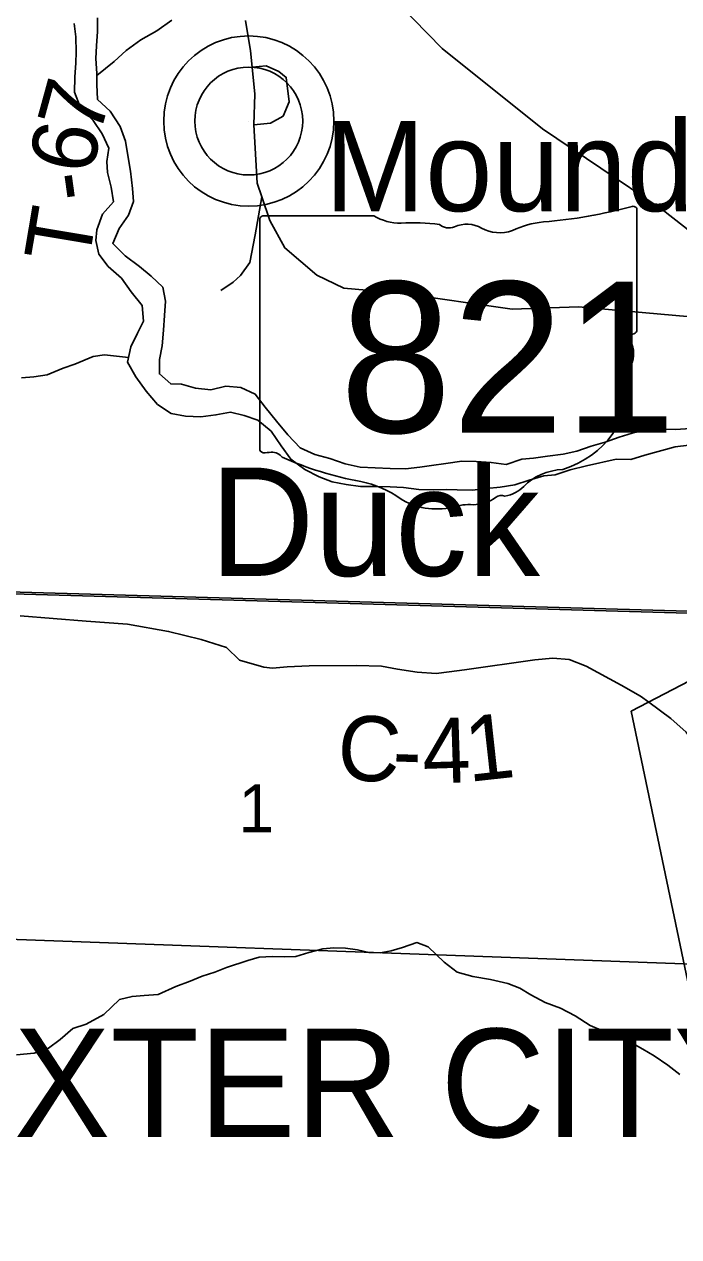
# Model space of a CAD drawing. Extents: x 2043100 to 2470832, y 443715 to 810583.
# Drawn here: x 2253891 to 2256911, y 603498 to 609094 of the extents above; entities that cross this region are included whole.
import ezdxf

# ---------------------------------------------------------------- set-up
doc = ezdxf.new("R2010")
doc.units = 0
for name, color, linetype in [('GM_X_City_Street', 7, 'Continuous'), ('GM_X_Corporation', 7, 'Continuous'), ('GM_X_Corporation_Text', 7, 'Continuous'), ('GM_X_County_Road', 7, 'Continuous'), ('GM_X_County_Road_Text', 7, 'Continuous'), ('GM_X_Interstate_Route', 7, 'Continuous'), ('GM_X_Major_River', 7, 'Continuous'), ('GM_X_Major_River_Text', 7, 'Continuous'), ('GM_X_Minor_River', 7, 'Continuous'), ('GM_X_Section', 7, 'Continuous'), ('GM_X_Section_Text', 7, 'Continuous'), ('GM_X_State_Location', 7, 'Continuous'), ('GM_X_State_Route', 7, 'Continuous'), ('GM_X_State_Shield', 7, 'Continuous'), ('GM_X_Township', 7, 'Continuous'), ('GM_X_Township_Road', 7, 'Continuous'), ('GM_X_Township_Road_Text', 7, 'Continuous'), ('GM_X_Unincorporated', 7, 'Continuous'), ('GM_X_Unincorporated_Location', 7, 'Continuous'), ('GM_X_Unincorporated_Text', 7, 'Continuous')]:
    doc.layers.add(name, color=color, linetype=linetype)

msp = doc.modelspace()

# ---------------------------------------------------------------- linework, layer by layer
at = {"layer": 'GM_X_City_Street'}
msp.add_lwpolyline([(2257564.9, 604475.8), (2257568.4, 604957), (2257562.2, 605061.7), (2257521.1, 605154.9), (2257489.2, 605199.6), (2257447, 605238.5), (2257232.7, 605495.2), (2257113.4, 605585.9), (2257038.7, 605696.3), (2256945.6, 605826.2), (2256874.1, 605890.6), (2256771.9, 605965)], dxfattribs=at)
at = {"layer": 'GM_X_Corporation'}
msp.add_lwpolyline([(2257301.8, 607165), (2257433.2, 607184.9), (2257564.2, 607172.1), (2257849.7, 607012.8), (2258169.6, 606695.9), (2258342.8, 606220.8), (2258433.8, 605737.6), (2258429.9, 605502.8), (2258330.3, 605083.1), (2258060.4, 604260), (2257007.1, 604418.1), (2256691.4, 605923.2), (2257425.1, 606304.7)], close=True, dxfattribs=at)
at = {"layer": 'GM_X_County_Road'}
msp.add_lwpolyline([(2256771.9, 605965), (2256733.8, 605992.9), (2256645.5, 606044.5), (2256483.1, 606131.8), (2256405, 606161.5), (2256329, 606169.1), (2256247, 606160.7), (2255921.3, 606114.9), (2255851.4, 606104.6), (2255791.4, 606098.3), (2255703.4, 606103.8), (2255613.4, 606117.4), (2255539.3, 606131), (2255423.3, 606134.4), (2255205.4, 606133.3), (2255103.4, 606128.8), (2255035.5, 606122.5), (2254995.5, 606126.3), (2254883.3, 606159.7), (2254823.1, 606217.4), (2254706.9, 606254.5), (2254556.8, 606291.6), (2254366.3, 606325.5), (2254175.9, 606338.4), (2253872.3, 606364.1)], dxfattribs=at)
at = {"layer": 'GM_X_Interstate_Route'}
for points in [[(2256820.8, 608248.8), (2256281.3, 608610.7), (2255819.7, 608981.8), (2255483, 609325.9), (2255208.6, 609680.6), (2255081.8, 609857.5), (2254809.8, 610236.7), (2254497, 610668), (2254433.9, 610754.9)], [(2259770.8, 601088.8), (2259641.3, 601435.9), (2259503.5, 601805.7), (2259377.8, 602171.6), (2259279.7, 602589.9), (2259219.7, 603030.6), (2259205, 603351.3), (2259231.4, 603804.8), (2259251.9, 604230.1), (2259282.1, 604713.7), (2259272.8, 605102.6), (2259223.5, 605461.2), (2259144.1, 605855), (2259047.4, 606089.8), (2258912.7, 606347.4), (2258714.1, 606642.4), (2258427.4, 606882.3), (2258115.4, 607148.3), (2257938.4, 607358.7), (2257653.2, 607589.5), (2257284.2, 607886.6), (2256834.5, 608239.7), (2256820.8, 608248.8)]]:
    msp.add_lwpolyline(points, dxfattribs=at)
at = {"layer": 'GM_X_Major_River'}
for points in [[(2254120.5, 609097.6), (2254129.2, 609035.6), (2254130.1, 608965.5), (2254128.6, 608915.4), (2254123.4, 608849.3), (2254122.2, 608781.2), (2254149, 608713.4), (2254207.9, 608650), (2254250.7, 608588.4), (2254281.5, 608522.7), (2254272.2, 608460.5), (2254274.8, 608410.4), (2254291.6, 608342.5), (2254302.4, 608274.5), (2254251, 608217.9), (2254225.8, 608145.5), (2254220.3, 608095.3), (2254235.1, 608033.4), (2254277.8, 607975.8), (2254338.6, 607922.5), (2254383.4, 607858.9), (2254434.3, 607795.4), (2254441.1, 607723.4), (2254413.7, 607669), (2254382.4, 607604.5), (2254367.2, 607534.2), (2254406, 607466.6), (2254452.9, 607401.1), (2254505.7, 607339.6), (2254568.3, 607298.3), (2254634.7, 607285), (2254704.9, 607281.8), (2254774.9, 607290.7), (2254842.9, 607303.5), (2254905.3, 607288.2), (2254967.7, 607266.9), (2255030.4, 607215.6), (2255075.3, 607148), (2255120.1, 607086.4), (2255184.8, 607039.1), (2255251.3, 607005.9), (2255311.8, 606982.5), (2255376.1, 606969.3), (2255442.3, 606960), (2255506.5, 606960.8), (2255578.6, 606959.7), (2255640.8, 606956.4), (2255711.1, 606947.2), (2255777.3, 606946), (2255837.4, 606946.7), (2255887.5, 606945.2), (2255957.7, 606944.1), (2256023.8, 606950.9), (2256085.9, 606957.6), (2256153.9, 606968.4), (2256219.8, 606989.2), (2256287.7, 607010), (2256339.8, 607014.7), (2256409.7, 607037.5), (2256485.7, 607056.4), (2256621.6, 607086.1), (2256689.8, 607084.9), (2256753.7, 607105.6), (2256893.6, 607143.3), (2256957.7, 607152.1)], [(2255370.9, 607065.4), (2255300.5, 607090.6), (2255232.1, 607107.8), (2255163.6, 607139), (2255106.8, 607198.4), (2255053.9, 607261.9), (2255003, 607327.4), (2254956.2, 607386.9), (2254889.7, 607418.2), (2254821.5, 607423.4), (2254751.5, 607406.6), (2254681.3, 607413.8), (2254616.9, 607433), (2254566.8, 607434.4), (2254514.1, 607479.9), (2254515.4, 607546), (2254526.6, 607610.2), (2254533.8, 607682.4), (2254537.1, 607750.5), (2254542.3, 607816.7), (2254529.5, 607880.7), (2254476.8, 607932.1), (2254422.2, 607975.5), (2254355.5, 608024.8), (2254298.7, 608082.2), (2254327.9, 608150.7), (2254371.3, 608213.3), (2254394.6, 608275.6), (2254389.9, 608335.7), (2254381, 608415.7), (2254370.2, 608479.7), (2254357.3, 608553.6), (2254332.5, 608621.4), (2254287.6, 608693), (2254228.8, 608746.4), (2254226, 608816.4), (2254225.4, 608866.5), (2254220.6, 608936.6), (2254223.9, 608994.7), (2254229.2, 609060.8), (2254228.5, 609122.9)], [(2256962.8, 607228.3), (2256896.7, 607223.5), (2256824.5, 607224.6), (2256760.4, 607221.9), (2256696.4, 607207.1), (2256636.5, 607188.4), (2256570.6, 607165.6), (2256506.7, 607146.8), (2256440.8, 607124), (2256376.8, 607109.2), (2256304.7, 607100.4), (2256240.7, 607091.6), (2256186.6, 607087), (2256114.7, 607062.1), (2256044.5, 607071.3), (2255976.2, 607076.5), (2255910.1, 607077.7), (2255836, 607066.8), (2255770, 607058), (2255715.9, 607049.4), (2255649.9, 607042.6), (2255579.7, 607043.8), (2255509.5, 607047), (2255441.3, 607050.2), (2255370.9, 607065.4)]]:
    msp.add_lwpolyline(points, dxfattribs=at)
at = {"layer": 'GM_X_Minor_River'}
for points in [[(2254225.5, 608857.8), (2254305.4, 608922.5), (2254361.2, 608972.9), (2254429, 609021.5), (2254502.9, 609064), (2254570.8, 609112.5)], [(2254371.9, 607556), (2254260.2, 607568.3), (2254208.1, 607560), (2254124.1, 607525.4), (2254070.1, 607507), (2253996.2, 607476.5), (2253934.1, 607466), (2253878, 607461.7)], [(2256916.3, 604247.1), (2256859.9, 604290.8), (2256797.5, 604332.5), (2256745.2, 604364.2), (2256688.8, 604395.8), (2256616.5, 604423.4), (2256552.1, 604451), (2256501.9, 604472.7), (2256433.4, 604518.3), (2256365, 604553.9), (2256294.7, 604579.5), (2256228.3, 604615.2), (2256178, 604644.8), (2256121.7, 604666.5), (2256041.4, 604686), (2255961.1, 604699.5), (2255888.8, 604719.1), (2255828.3, 604764.7), (2255753.7, 604836.3), (2255701.4, 604856), (2255635.4, 604833.6), (2255583.4, 604817.2), (2255533.3, 604808.9), (2255481.2, 604810.5), (2255429, 604822.2), (2255372.8, 604829.8), (2255318.7, 604831.5), (2255268.6, 604827.2), (2255204.5, 604810.7), (2255144.5, 604792.3), (2255090.4, 604789.9), (2255036.3, 604791.6), (2254974.1, 604789.2), (2254922.1, 604772.8), (2254824.1, 604740.2), (2254770.1, 604719.8), (2254712.1, 604701.4), (2254656.1, 604677), (2254590.1, 604652.5), (2254508.2, 604615.9), (2254444, 604611.5), (2254387.9, 604607.1), (2254329.9, 604592.7), (2254258.2, 604524.2), (2254176.3, 604479.6), (2254114.3, 604459.2), (2254056.4, 604408.7), (2254002.6, 604368.3), (2253936.6, 604345.8), (2253854.4, 604337.3)]]:
    msp.add_lwpolyline(points, dxfattribs=at)
at = {"layer": 'GM_X_Section'}
for points in [[(2257692.8, 611847.6), (2257691.4, 611621.5), (2257601.2, 606366.3), (2252357.3, 606516.7), (2252408.2, 612055.5)], [(2252357.3, 606516.7), (2257601.2, 606366.3), (2257566.4, 604734.7), (2252340.1, 604925.8)]]:
    msp.add_lwpolyline(points, close=True, dxfattribs=at)
at = {"layer": 'GM_X_State_Route'}
msp.add_lwpolyline([(2257548.1, 607244.4), (2257547.8, 607245.7), (2257477, 607404.3), (2257445.3, 607484.8), (2257364.7, 607570.2), (2257265.6, 607654.2), (2257154.1, 607710), (2257035.2, 607737.9), (2256447.9, 607789.9), (2256142.1, 607779.8), (2255626.9, 607853.6), (2255365.4, 607876.5), (2255240.4, 607936.1), (2255093, 608061.8), (2255024, 608187.8), (2254986.1, 608298.2), (2254964.9, 608360), (2254950, 608630.3), (2254954.9, 608771.1), (2254941.9, 608895.4), (2254933.9, 608971.6), (2254911.1, 609111.8)], dxfattribs=at)
at = {"layer": 'GM_X_State_Shield'}
for p, q in [((2255504.3, 608209.7), (2254994.7, 608209.7)), ((2256717.8, 607683.1), (2256717.8, 608235.9)), ((2254977.6, 608191.5), (2254977.6, 607134.9)), ((2256717.6, 607683.3), (2256717.8, 607683.1))]:
    msp.add_line(p, q, dxfattribs=at)
for centre, major_axis, start_param, end_param in [((2256097.9, 609650.2), (1845.5, 0), 4.814394, 5.042369), ((2256698.5, 608238.2), (19.4, 0), 6.141152, 7.989035), ((2254997.5, 608193.8), (20.2, 0), 1.712693, 3.28349), ((2255625.7, 608332.4), (195.5, 0), 4.042523, 4.731795), ((2255690.5, 607616.5), (702, 0), 1.404758, 1.657858), ((2255849.9, 608199.2), (56.4, 0), 3.836095, 5.185415), ((2255932.7, 608077.1), (117.3, 0), 0.950623, 2.079405), ((2256084.1, 608244.6), (141.1, 0), 4.081561, 5.145723), ((2256333.3, 607887), (371.3, 0), 1.699011, 2.107814), ((2256713.3, 607642.6), (30, 0), 1.883978, 3.671073), ((2256697.1, 607681), (20.7, 0), 5.05454, 6.418171), ((2256522.6, 607572.7), (180, 0), 5.934695, 6.695948), ((2256787.2, 607451.8), (130.9, 0), 2.387724, 3.262537), ((2256201.3, 607381.5), (461.6, 0), 5.101752, 6.440018), ((2254997.7, 607132.6), (20.3, 0), 3.00124, 4.508301), ((2255000.8, 607240.7), (155.2, 0), 4.665946, 4.897461), ((2255032.5, 607073.9), (56, 0), 0.519207, 1.627899), ((2255739.1, 608023.3), (1332.7, 0), 4.195997, 4.488961), ((2256395.9, 606838.2), (252.8, 0), 1.647645, 2.488434), ((2255341.8, 606660.2), (417, 0), 0.823519, 1.323587), ((2255965, 606989.5), (141, 0), 4.691044, 5.507374), ((2256092.5, 606887.2), (39.7, 0), 1.147584, 2.315152), ((2256075.6, 607032.5), (149.1, 0), 4.937069, 5.64225), ((2255792.8, 607068.7), (264.6, 0), 4.026481, 4.996735), ((2255945.7, 606703.3), (217.4, 0), 1.495662, 1.94098)]:
    msp.add_ellipse(centre, major_axis=major_axis, ratio=0.8, start_param=start_param, end_param=end_param, dxfattribs=at)
at = {"layer": 'GM_X_Township'}
for points in [[(2258081.3, 633732.5), (2257992.6, 628603.2), (2257760.5, 615186.1), (2257653.2, 607589.5), (2257624.6, 606994.4), (2257596.4, 606358.1), (2253890.2, 606463.4), (2249021.7, 606637.8), (2248304.7, 606663.3), (2243521.3, 606786.8), (2239722.4, 606909.9), (2234400.7, 607082.4), (2233675.1, 607105.9), (2233758.1, 612789.2), (2233874.4, 620743.5), (2233877.9, 620982.4), (2233882.7, 621311.5), (2233884.4, 621427.4), (2233890.3, 621836.9), (2233896.9, 622286.3), (2233904.3, 622790.6), (2233907.5, 623014), (2234072.5, 630720.1), (2234171.5, 633589.1)], [(2234400.7, 607082.4), (2239722.4, 606909.9), (2243521.3, 606786.8), (2248304.7, 606663.3), (2249021.7, 606637.8), (2253890.2, 606463.4), (2257596.4, 606358.1), (2257565.4, 605638.9), (2257563.6, 605306.8), (2257562.2, 605061.7), (2257568.4, 604957), (2257564.9, 604475.8), (2257574, 602803.7), (2257579.2, 602655.8), (2257603, 601401.2), (2257611.2, 601163.6), (2257605.5, 595412.8)]]:
    msp.add_lwpolyline(points, dxfattribs=at)
at = {"layer": 'GM_X_Township_Road'}
for points in [[(2254950, 608630.3), (2255026.3, 608636.8), (2255085.9, 608669.9), (2255112.4, 608736.2), (2255099.2, 608848.9), (2255066, 608875.4), (2255006.4, 608901.9), (2254941.9, 608895.4)], [(2254798.4, 607865.4), (2254854.7, 607903.1), (2254888.9, 607934.9), (2254931.3, 607994.7), (2254956.1, 608122.8), (2254986.1, 608298.2)]]:
    msp.add_lwpolyline(points, dxfattribs=at)
at = {"layer": 'GM_X_Unincorporated'}
for radius in [392.8, 249]:
    msp.add_circle((2254926.7, 608647.3), radius, dxfattribs=at)
at = {"layer": 'GM_X_Unincorporated_Location'}
msp.add_line((2254926.7, 608647.3), (2254926.7, 608647.3), dxfattribs=at)

# ---------------------------------------------------------------- texts
at = {"layer": 'GM_X_Corporation_Text'}
msp.add_text('DEXTER CITY', height=500, rotation=0, dxfattribs=at).set_placement((2252913.3, 603958.1))
at = {"layer": 'GM_X_County_Road_Text'}
for s, rotation, p in [('C', 355.5657, (2255326.6, 605613.2)), ('1', 6.2671, (2255941.2, 605596.9)), ('4', 1.8336, (2255731.2, 605589.2)), ('-', 358.0827, (2255586.6, 605593.4))]:
    msp.add_text(s, height=300, rotation=rotation, dxfattribs=at).set_placement(p)
at = {"layer": 'GM_X_Major_River_Text'}
msp.add_text('Duck', height=499.98, rotation=0.0012, dxfattribs=at).set_placement((2254746.5, 606548.1))
at = {"layer": 'GM_X_Section_Text'}
msp.add_text('1', height=220.8, rotation=0, dxfattribs=at).set_placement((2254878.8, 605365.2))
at = {"layer": 'GM_X_State_Location'}
for s in ['s', 'r']:
    msp.add_text(s, height=0.0000833, dxfattribs=at).set_placement((2255828.3, 607593.4))
msp.add_text('821', height=0.0000833, rotation=0, dxfattribs=at).set_placement((2255475, 607520.2))
at = {"layer": 'GM_X_State_Shield'}
msp.add_text('821', height=696.1, dxfattribs=at).set_placement((2255345.9, 607209.4))
at = {"layer": 'GM_X_Township_Road_Text'}
for s, rotation, p in [('7', 74.6636, (2254236.7, 608568.7)), ('6', 80.1313, (2254206.7, 608394)), ('-', 97.8258, (2254223.9, 608296.3)), ('T', 80.4637, (2254185.2, 607976.3))]:
    msp.add_text(s, height=300, rotation=rotation, dxfattribs=at).set_placement(p)
at = {"layer": 'GM_X_Unincorporated_Text'}
msp.add_text('Moundsville', height=416.667, rotation=0, dxfattribs=at).set_placement((2255277, 608231.3))

doc.saveas('drawing.dxf')
